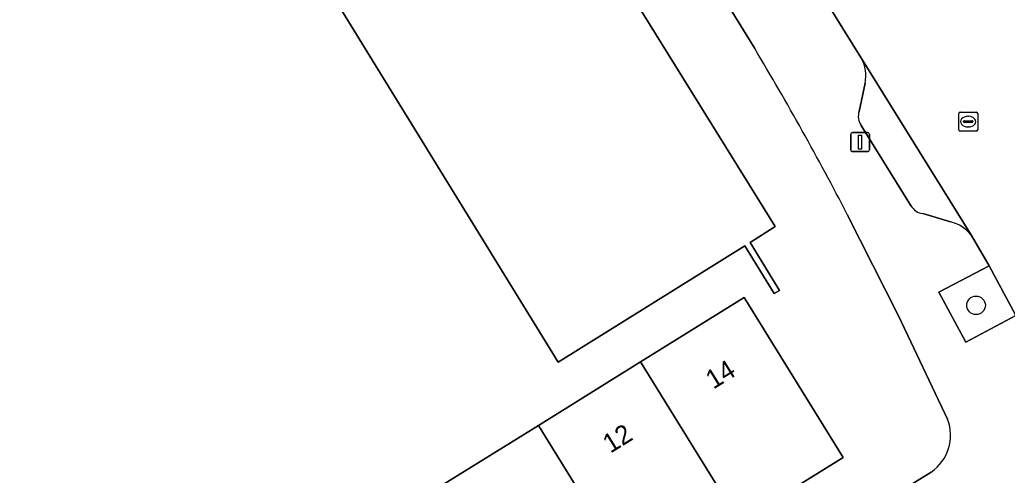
# Model space of a CAD drawing. Extents: x 160030 to 160839, y 385325 to 386450.
# Drawn here: x 160333.6 to 160385.7, y 386216.1 to 386240.2 of the extents above; entities that cross this region are included whole.
import ezdxf

# ---------------------------------------------------------------- set-up
doc = ezdxf.new("R2010")
doc.units = 0
for name, color, linetype in [('IMGEO_Boom', 7, 'Continuous'), ('IMGEO_Erf', 7, 'Continuous'), ('IMGEO_Groenvoorziening', 7, 'Continuous'), ('IMGEO_Lichtmast', 7, 'Continuous'), ('IMGEO_Pand', 7, 'Continuous'), ('IMGEO_Pand_nummerreeks', 7, 'Continuous'), ('IMGEO_Parkeervlak_open', 7, 'Continuous'), ('IMGEO_Rijbaan_lokaal_open', 7, 'Continuous'), ('IMGEO_Rioolput', 7, 'Continuous'), ('IMGEO_Voetpad_open', 7, 'Continuous')]:
    doc.layers.add(name, color=color, linetype=linetype)

msp = doc.modelspace()

# ---------------------------------------------------------------- linework, layer by layer
at = {"layer": 'IMGEO_Boom'}
msp.add_circle((160384.102, 386225.102), 0.489, dxfattribs=at)
at = {"layer": 'IMGEO_Erf'}
for points in [[(160372.421, 386238.639), (160365.405, 386250), (160351.069, 386273.213)], [(160382.596, 386219.091), (160380.001, 386224.547), (160377.306, 386229.897)], [(160339.732, 386190.285), (160379.488, 386214.921), (160381.729, 386216.309)]]:
    msp.add_lwpolyline(points, dxfattribs=at)
for points in [[(160346.068, 386248.087), (160349.161, 386250), (160349.371, 386250.13), (160346.994, 386253.981), (160340.58, 386250), (160314.356, 386233.725), (160307.279, 386245.109), (160315.164, 386250), (160346.657, 386269.536), (160350.096, 386263.95), (160349.044, 386263.274), (160350.863, 386260.319), (160350.868, 386260.31), (160352.434, 386257.766), (160353.531, 386258.466), (160354.989, 386256.082), (160356.33, 386256.943), (160360.635, 386250), (160373.503, 386229.25), (160372.174, 386228.406), (160373.739, 386225.879), (160373.455, 386225.72), (160371.898, 386228.234), (160362.051, 386222.095)], [(160350.222, 386212.061), (160355.614, 386215.415), (160361.006, 386218.769), (160366.398, 386222.123), (160371.861, 386225.521), (160377.096, 386217.071), (160371.616, 386213.678), (160366.217, 386210.336), (160360.818, 386206.994), (160355.418, 386203.651), (160350.019, 386200.309), (160344.62, 386196.966), (160339.221, 386193.624), (160334.046, 386201.999), (160339.438, 386205.353), (160344.83, 386208.707)]]:
    msp.add_lwpolyline(points, close=True, dxfattribs=at)
for centre, radius, start, end in [((160239.073, 386158.389), 155.633, 27.35263, 31.03999), ((160380.422, 386218.242), 2.334, 304.0612, 21.3198)]:
    msp.add_arc(centre, radius, start, end, dxfattribs=at)
at = {"layer": 'IMGEO_Groenvoorziening'}
msp.add_lwpolyline([(160386.199, 386224.569), (160384.799, 386227.189), (160382.142, 386225.798), (160383.555, 386223.155)], close=True, dxfattribs=at)
at = {"layer": 'IMGEO_Lichtmast'}
for p, q in [((160377.486, 386233.308), (160377.486, 386234.108)), ((160377.486, 386234.108), (160377.486, 386233.308)), ((160377.586, 386234.208), (160378.376, 386234.208)), ((160378.376, 386234.208), (160377.586, 386234.208)), ((160378.476, 386234.108), (160378.476, 386233.308)), ((160378.476, 386233.308), (160378.476, 386234.108)), ((160378.376, 386233.208), (160377.586, 386233.208)), ((160377.586, 386233.208), (160378.376, 386233.208))]:
    msp.add_line(p, q, dxfattribs=at)
msp.add_lwpolyline([(160377.906, 386234.083), (160378.056, 386234.083), (160378.056, 386233.333), (160377.906, 386233.333), (160377.906, 386234.083)], dxfattribs=at)
for centre, start, end in [((160377.586, 386234.108), 90, 180), ((160377.586, 386234.108), 90, 180), ((160378.376, 386234.108), 0, 90), ((160378.376, 386234.108), 360, 90), ((160377.586, 386233.308), 180, 270), ((160377.586, 386233.308), 180, 270), ((160378.376, 386233.308), 270, 0), ((160378.376, 386233.308), 270, 0)]:
    msp.add_arc(centre, 0.1, start, end, dxfattribs=at)
at = {"layer": 'IMGEO_Pand'}
for points in [[(160360.635, 386250), (160356.33, 386256.943), (160354.989, 386256.082), (160353.531, 386258.466), (160352.434, 386257.766), (160350.868, 386260.31), (160350.863, 386260.319), (160349.044, 386263.274), (160350.096, 386263.95), (160346.657, 386269.536), (160315.164, 386250), (160307.279, 386245.109), (160314.356, 386233.725), (160340.58, 386250), (160346.994, 386253.981), (160349.371, 386250.13), (160349.161, 386250), (160346.068, 386248.087), (160362.051, 386222.095), (160371.898, 386228.234), (160373.455, 386225.72), (160373.739, 386225.879), (160372.174, 386228.406), (160373.503, 386229.25)], [(160377.096, 386217.071), (160371.861, 386225.521), (160366.398, 386222.123), (160371.616, 386213.678)], [(160371.616, 386213.678), (160366.398, 386222.123), (160361.006, 386218.769), (160366.217, 386210.336)], [(160366.217, 386210.336), (160361.006, 386218.769), (160355.614, 386215.415), (160360.818, 386206.994)]]:
    msp.add_lwpolyline(points, close=True, dxfattribs=at)
at = {"layer": 'IMGEO_Parkeervlak_open'}
for points in [[(160383.862, 386228.788), (160378.049, 386238.126)], [(160378.245, 386236.819), (160377.926, 386235.331)], [(160378.034, 386234.586), (160380.679, 386230.333)], [(160381.287, 386229.945), (160382.754, 386229.509)]]:
    msp.add_lwpolyline(points, dxfattribs=at)
for centre, radius, start, end in [((160376.489, 386237.224), 1.802, 347.0181, 30.0391), ((160378.774, 386235.074), 0.886, 163.1063, 213.3908), ((160381.369, 386230.745), 0.804, 210.7981, 264.1133), ((160382.211, 386227.463), 2.117, 38.7568, 75.1373)]:
    msp.add_arc(centre, radius, start, end, dxfattribs=at)
at = {"layer": 'IMGEO_Rijbaan_lokaal_open'}
msp.add_lwpolyline([(160354.036, 386276.982), (160354.153, 386276.793), (160359.823, 386267.623), (160362.326, 386263.486), (160368.126, 386254.151), (160369.836, 386251.393), (160375.678, 386241.955), (160378.049, 386238.126), (160383.862, 386228.788), (160384.799, 386227.189), (160386.199, 386224.569), (160387.779, 386221.116)], dxfattribs=at)
at = {"layer": 'IMGEO_Rioolput'}
for p, q in [((160383.185, 386234.363), (160383.185, 386235.215)), ((160383.26, 386235.289), (160384.112, 386235.289)), ((160383.673, 386235.069), (160383.698, 386235.069)), ((160384.186, 386235.215), (160384.186, 386234.363)), ((160383.444, 386234.783), (160383.444, 386234.795)), ((160383.882, 386234.746), (160383.484, 386234.746)), ((160383.487, 386234.832), (160383.885, 386234.832)), ((160383.696, 386234.509), (160383.671, 386234.509)), ((160383.928, 386234.795), (160383.928, 386234.783)), ((160384.112, 386234.289), (160383.26, 386234.289))]:
    msp.add_line(p, q, dxfattribs=at)
for points in [[(160383.185, 386234.363), (160383.185, 386235.215)], [(160383.26, 386235.289), (160384.112, 386235.289)], [(160384.186, 386235.215), (160384.186, 386234.363)], [(160384.112, 386234.289), (160383.26, 386234.289)]]:
    msp.add_lwpolyline(points, dxfattribs=at)
for centre, radius, start, end in [((160383.262, 386235.213), 0.0765, 91.552, 178.448), ((160383.262, 386235.213), 0.0765, 91.552, 178.448), ((160384.11, 386235.213), 0.0765, 1.552, 88.448), ((160384.11, 386235.213), 0.0765, 1.552, 88.448), ((160383.262, 386234.365), 0.0765, 181.552, 268.448), ((160383.262, 386234.365), 0.0765, 181.552, 268.448), ((160383.484, 386234.792), 0.0403, 85.8775, 175.7526), ((160383.481, 386234.782), 0.0366, 178.938, 274.7102), ((160383.885, 386234.789), 0.043, 264.8664, 352.4533), ((160383.889, 386234.794), 0.0386, 1.7309, 96.639), ((160384.11, 386234.365), 0.0765, 271.552, 358.448), ((160384.11, 386234.365), 0.0765, 271.552, 358.448)]:
    msp.add_arc(centre, radius, start, end, dxfattribs=at)
for centre, major_axis, ratio, start_param, end_param in [((160383.672, 386234.789), (-0.387, 0.002), 0.722429, 4.712389, 7.853982), ((160383.697, 386234.789), (-0.39, 0.002), 0.717154, 1.570796, 4.712389)]:
    msp.add_ellipse(centre, major_axis=major_axis, ratio=ratio, start_param=start_param, end_param=end_param, dxfattribs=at)
at = {"layer": 'IMGEO_Voetpad_open'}
for points in [[(160351.069, 386273.213), (160365.405, 386250), (160372.421, 386238.639)], [(160378.049, 386238.126), (160375.678, 386241.955)], [(160377.926, 386235.331), (160378.245, 386236.819)], [(160380.679, 386230.333), (160378.034, 386234.586)], [(160377.306, 386229.897), (160380.001, 386224.547), (160382.596, 386219.091)], [(160382.754, 386229.509), (160381.287, 386229.945)], [(160387.779, 386221.116), (160386.199, 386224.569), (160383.555, 386223.155), (160382.142, 386225.798), (160384.799, 386227.189), (160383.862, 386228.788)], [(160381.729, 386216.309), (160379.488, 386214.921), (160381.865, 386211.269), (160385.586, 386213.593)]]:
    msp.add_lwpolyline(points, dxfattribs=at)
for centre, radius, start, end in [((160239.073, 386158.389), 155.633, 27.35263, 31.03999), ((160376.489, 386237.224), 1.802, 347.0181, 30.0391), ((160378.774, 386235.074), 0.886, 163.1063, 213.3908), ((160381.369, 386230.745), 0.804, 210.7981, 264.1133), ((160382.211, 386227.463), 2.117, 38.7568, 75.1373), ((160380.422, 386218.242), 2.334, 304.0612, 21.3198)]:
    msp.add_arc(centre, radius, start, end, dxfattribs=at)

# ---------------------------------------------------------------- texts
at = {"layer": 'IMGEO_Pand_nummerreeks'}
for s, p in [('14', (160370.24, 386220.65)), ('12', (160364.807, 386217.271))]:
    msp.add_text(s, height=1, rotation=31.8828, dxfattribs=at).set_placement(p)

doc.saveas('drawing.dxf')
